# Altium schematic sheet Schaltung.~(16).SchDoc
size A4
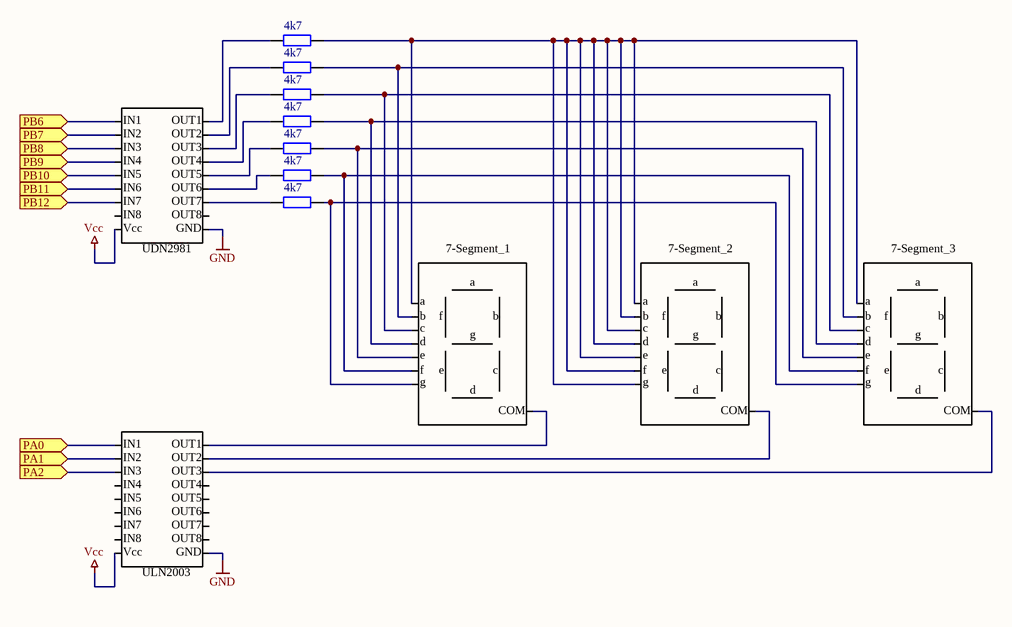
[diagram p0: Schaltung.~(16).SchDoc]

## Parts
R1  value 4k7  [AXIAL-0.4]  (hidden comment: Res2)
R2  value 4k7  [AXIAL-0.4]  (hidden comment: Res2)
R3  value 4k7  [AXIAL-0.4]  (hidden comment: Res2)
R4  value 4k7  [AXIAL-0.4]  (hidden comment: Res2)
R5  value 4k7  [AXIAL-0.4]  (hidden comment: Res2)
R6  value 4k7  [AXIAL-0.4]  (hidden comment: Res2)
R7  value 4k7  [AXIAL-0.4]  (hidden comment: Res2)

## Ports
PA0, PA1, PA2, PB6, PB7, PB8, PB9, PB10, PB11, PB12

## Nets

Not connected (* = marked no-connect by the designer): R1 1 2; R2 1 2; R3 1 2; R4 1 2; R5 1 2; R6 1 2; R7 1 2

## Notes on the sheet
- IN1
- IN2
- IN3
- IN4
- IN5
- IN6
- OUT1
- OUT2
- OUT3
- OUT4
- OUT5
- OUT6
- IN7
- IN8
- Vcc
- UDN2981
- OUT7
- OUT8
- GND
- 7-Segment_1
- 7-Segment_2
- 7-Segment_3
- a
- b
- f
- c
- d
- e
- g
- COM
- ULN2003

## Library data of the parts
R1-R7 = Res2: Resistor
